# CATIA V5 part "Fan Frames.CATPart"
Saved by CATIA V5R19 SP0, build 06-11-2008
Part number: Fan Frames
Bounding box of the stored display mesh (mm): x -45.5 to 45.5, y -12.5 to 12.5, z -45.5 to 45.5
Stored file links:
  D:\Lectures\Catia DMU Lecture Notes\Practice Files\Revolute Joint\Electric Fan\Result\Electric Fan Assembly with No SubAssembly\Fan Frames.CATPart
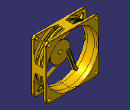
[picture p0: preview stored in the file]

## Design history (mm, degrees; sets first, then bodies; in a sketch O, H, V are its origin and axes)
Body1 "Fan Frames" (main body)
  Solid1: solid without history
